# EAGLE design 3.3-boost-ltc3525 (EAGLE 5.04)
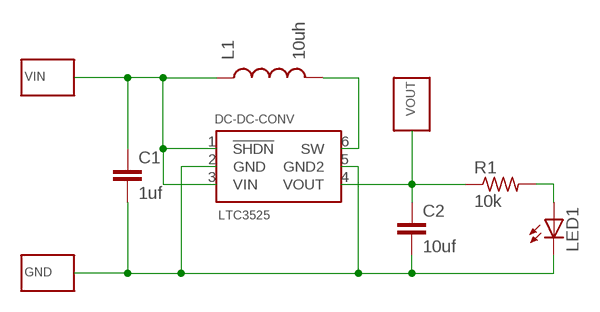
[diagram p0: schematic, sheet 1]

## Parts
C1  1uf  C-EUC1206  [C1206]
C2  10uf  C-EUC1206  [C1206]
DC-DC-CONV  LTC3525  [SC70-6]
GND  WIREPAD-SMD-NO-VALUE  [WIREPAD-SMD]
L1  10uh  INDUCTOR1210  [1210]
LED1  LEDCHIPLED_0805  [CHIPLED_0805]
R1  10k  R-US_R0603  [R0603]
VIN  WIREPAD-SMD-NO-VALUE  [WIREPAD-SMD]
VOUT  WIREPAD-SMD-NO-VALUE  [WIREPAD-SMD]

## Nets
N$1: C1.1 DC-DC-CONV.1(!SHDN) DC-DC-CONV.3(VIN) L1.1 VIN.1(P)
N$2: DC-DC-CONV.6(SW) L1.2
N$3: C2.1 DC-DC-CONV.4(VOUT) R1.1 VOUT.1(P)
N$4: C1.2 C2.2 DC-DC-CONV.2(GND) DC-DC-CONV.5(GND2) GND.1(P) LED1.C
N$5: LED1.A R1.2

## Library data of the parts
C1 C2 = rcl:C-EU: CAPACITOR, European symbol
DC-DC-CONV = trl:LTC3525
GND VIN VOUT = trl:WIREPAD-SMD-NO-VALUE
L1 = SparkFun:INDUCTOR: Inductors
LED1 = led:LED: LED
R1 = resistor:R-US_: RESISTOR, American symbol

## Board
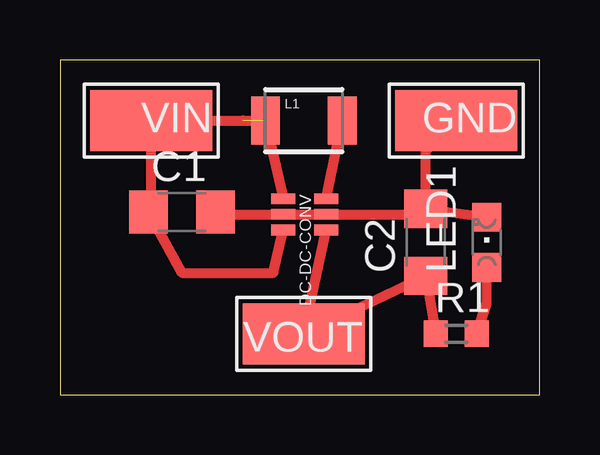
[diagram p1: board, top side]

Size 19.99 x 13.96 mm. Coordinates in mm from the lower left corner, seen from the top.
Outline: 0,0 19.99,0 19.99,13.96 0,13.96 0,0
Copper layers (1*16): Top 0.035mm / dielectric 1.5mm / Bottom 0.035mm
Design rules "default": minimum track width 10mil, minimum drill 24mil, track to track 8mil, track to pad 8mil, pad to pad 8mil, via to via 8mil, smd to smd 8mil, copper to edge 40mil, drill to drill 8mil, minimum pad ring 10mil, minimum via ring 8mil, stop-mask expansion 4mil, vias tented up to drill 0mil, thermal gap 10mil

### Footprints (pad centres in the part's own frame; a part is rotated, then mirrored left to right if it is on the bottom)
C1206 = smd 1.6 x 1.8: 1 -1.4,0; 2 1.4,0
SC70-6 = smd 0.45 x 1: 1 -0.55,-0.85; 2 0.1,-0.85; 3 0.75,-0.85; 4 0.75,0.94; 5 0.1,0.94; 6 -0.55,0.94
WIREPAD-SMD = smd 2.54 x 5.08: 1 0,0
1210 = smd 1.2 x 2: 1 -1.6,0; 2 1.6,0
CHIPLED_0805 = smd 1.2 x 1.2: A 0,-1.05; C 0,1.05
R0603 = smd 1 x 1.1: 1 -0.85,0; 2 0.85,0

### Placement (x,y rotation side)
C1  5.08,7.62 0 top
C2  15.24,6.35 90 top
DC-DC-CONV  10.16,7.62 270 top
GND  16.51,11.43 90 top
L1  10.16,11.43 0 top
LED1  17.78,6.35 0 top
R1  16.51,2.54 0 top
VIN  3.81,11.43 90 top
VOUT  10.16,2.54 270 top

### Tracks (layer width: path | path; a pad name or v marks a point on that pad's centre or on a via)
N$1  (1 unrouted)
  Top 0.254: C1.1 3.81,7.62 | L1.1 7.62,11.43 | VIN.1 5.08,11.43
  Top 0.406: 3.81,7.62 VIN.1 | 5.08,11.43 7.62,11.43 L1.1 DC-DC-CONV.1 | DC-DC-CONV.3 8.89,5.08 5.08,5.08 C1.1
N$2
  Top 0.406: DC-DC-CONV.6 L1.2
N$3
  Top 0.406: DC-DC-CONV.4 VOUT.1 C2.1 R1.1
N$4
  Top 0.406: 15.24,7.62 15.24,10.16 GND.1 | 15.24,7.62 C2.2 LED1.C | C1.2 6.48,7.52 DC-DC-CONV.2 DC-DC-CONV.5 15.24,7.52 15.24,7.62
N$5
  Top 0.254: 17.78,5.08 LED1.A
  Top 0.406: 17.78,5.08 17.78,3.81 R1.2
